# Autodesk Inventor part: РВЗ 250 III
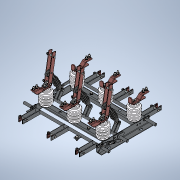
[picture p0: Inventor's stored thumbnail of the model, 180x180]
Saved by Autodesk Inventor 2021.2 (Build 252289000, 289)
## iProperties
Created: 1900-01
Part Number: РВЗ 250 III
Material: Типовые
Description: STEP AP242
Document SubType Name: Modeling
Designer: pc
Density: 1 g/cm^3
Appearance: По умолчанию
Company: UNSPECIFIED
Title: ÐÂÇ 250 III
Author: UNSPECIFIED
Revision Number: ANYUNSPECIFIED
Sending System: C3D Toolkit
Preprocessor: C3D Converter
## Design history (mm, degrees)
feature "БазТело1"
feature "БазТело2"
feature "БазТело3"
feature "БазТело4"
feature "БазТело5"
feature "БазТело6"
feature "Составной1"
node "Твердое тело1"
node "Твердое тело2"
node "Твердое тело3"
node "Твердое тело4"
node "Твердое тело5"
node "Твердое тело6"
body "SRF1"
